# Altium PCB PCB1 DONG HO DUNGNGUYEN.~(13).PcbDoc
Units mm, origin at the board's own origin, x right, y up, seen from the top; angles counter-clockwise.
Board outline 60.96 x 45.72 mm, 2 copper layers (Top Layer, Bottom Layer); 0 components, 3 nets, 0 pads, 0 vias.
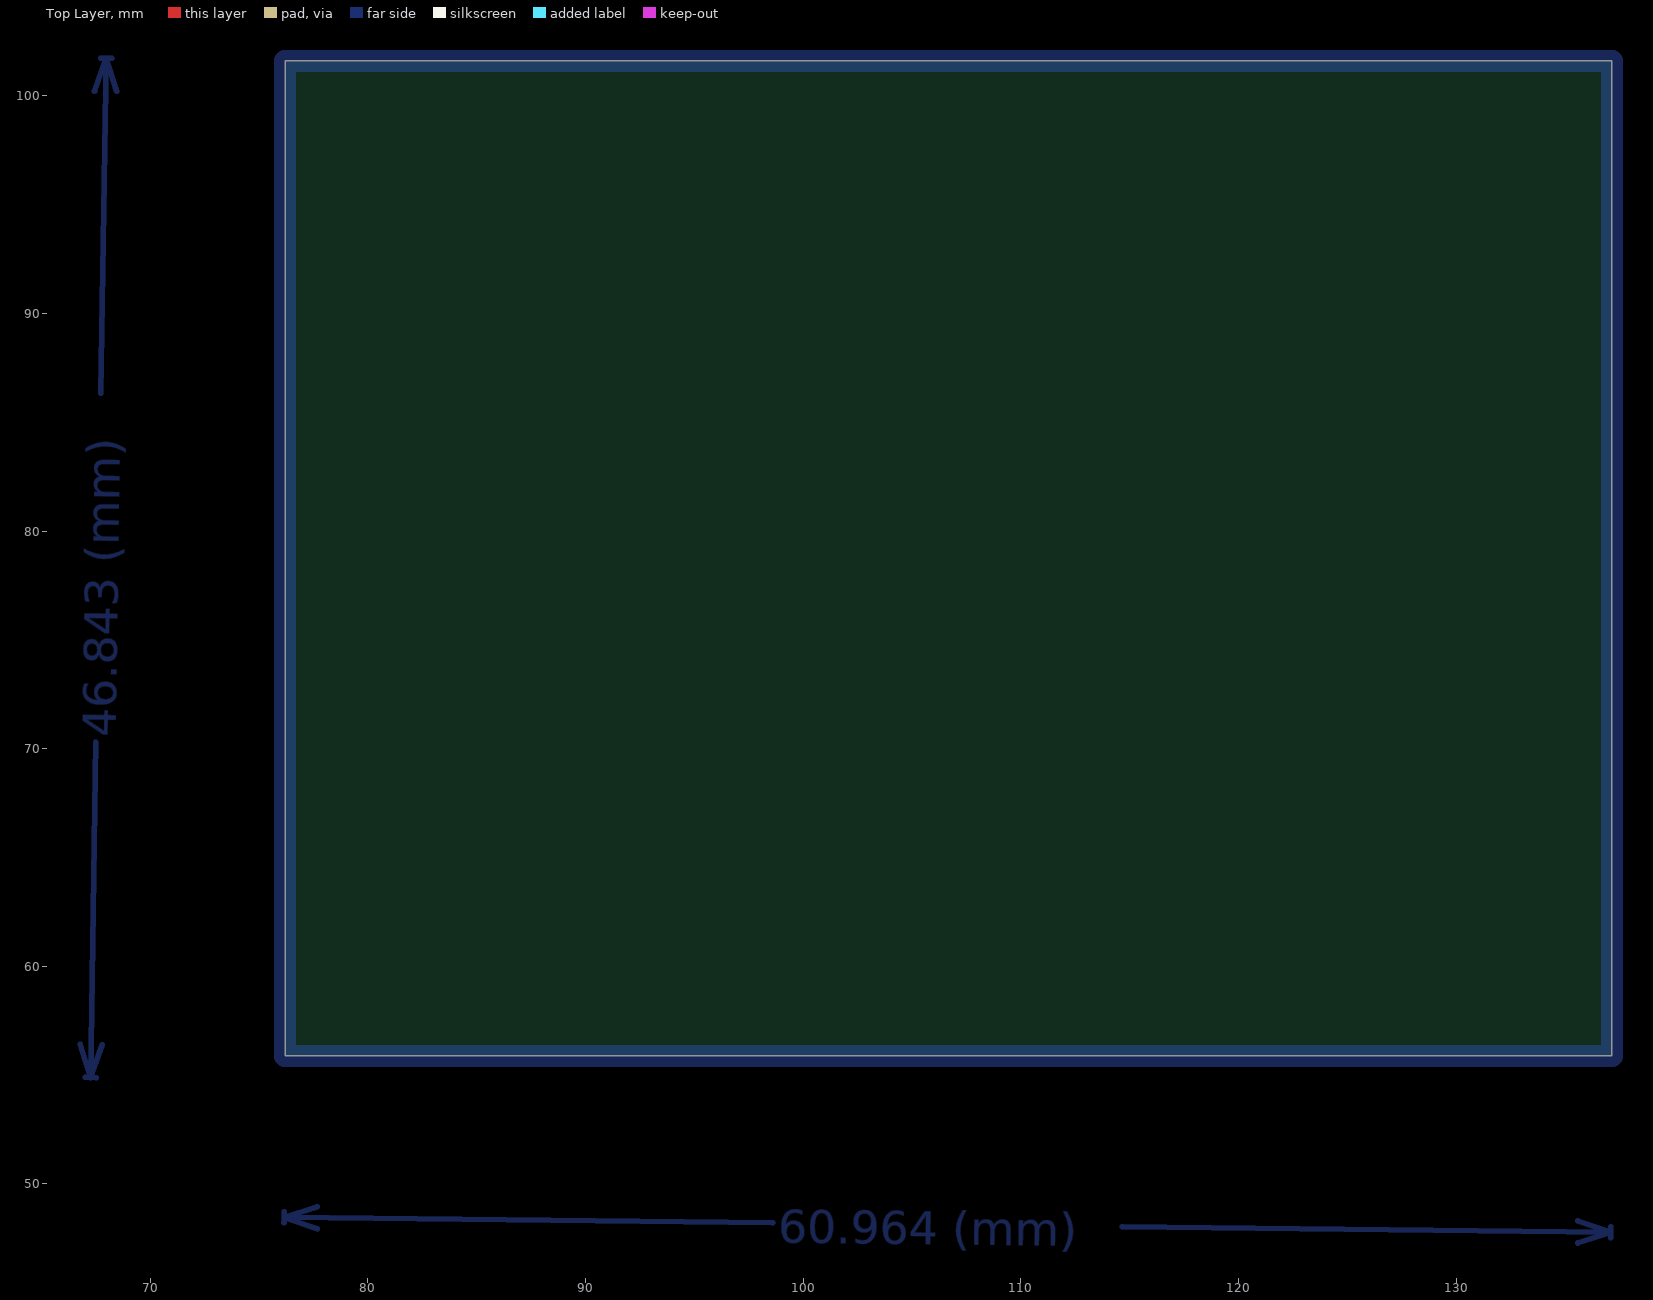
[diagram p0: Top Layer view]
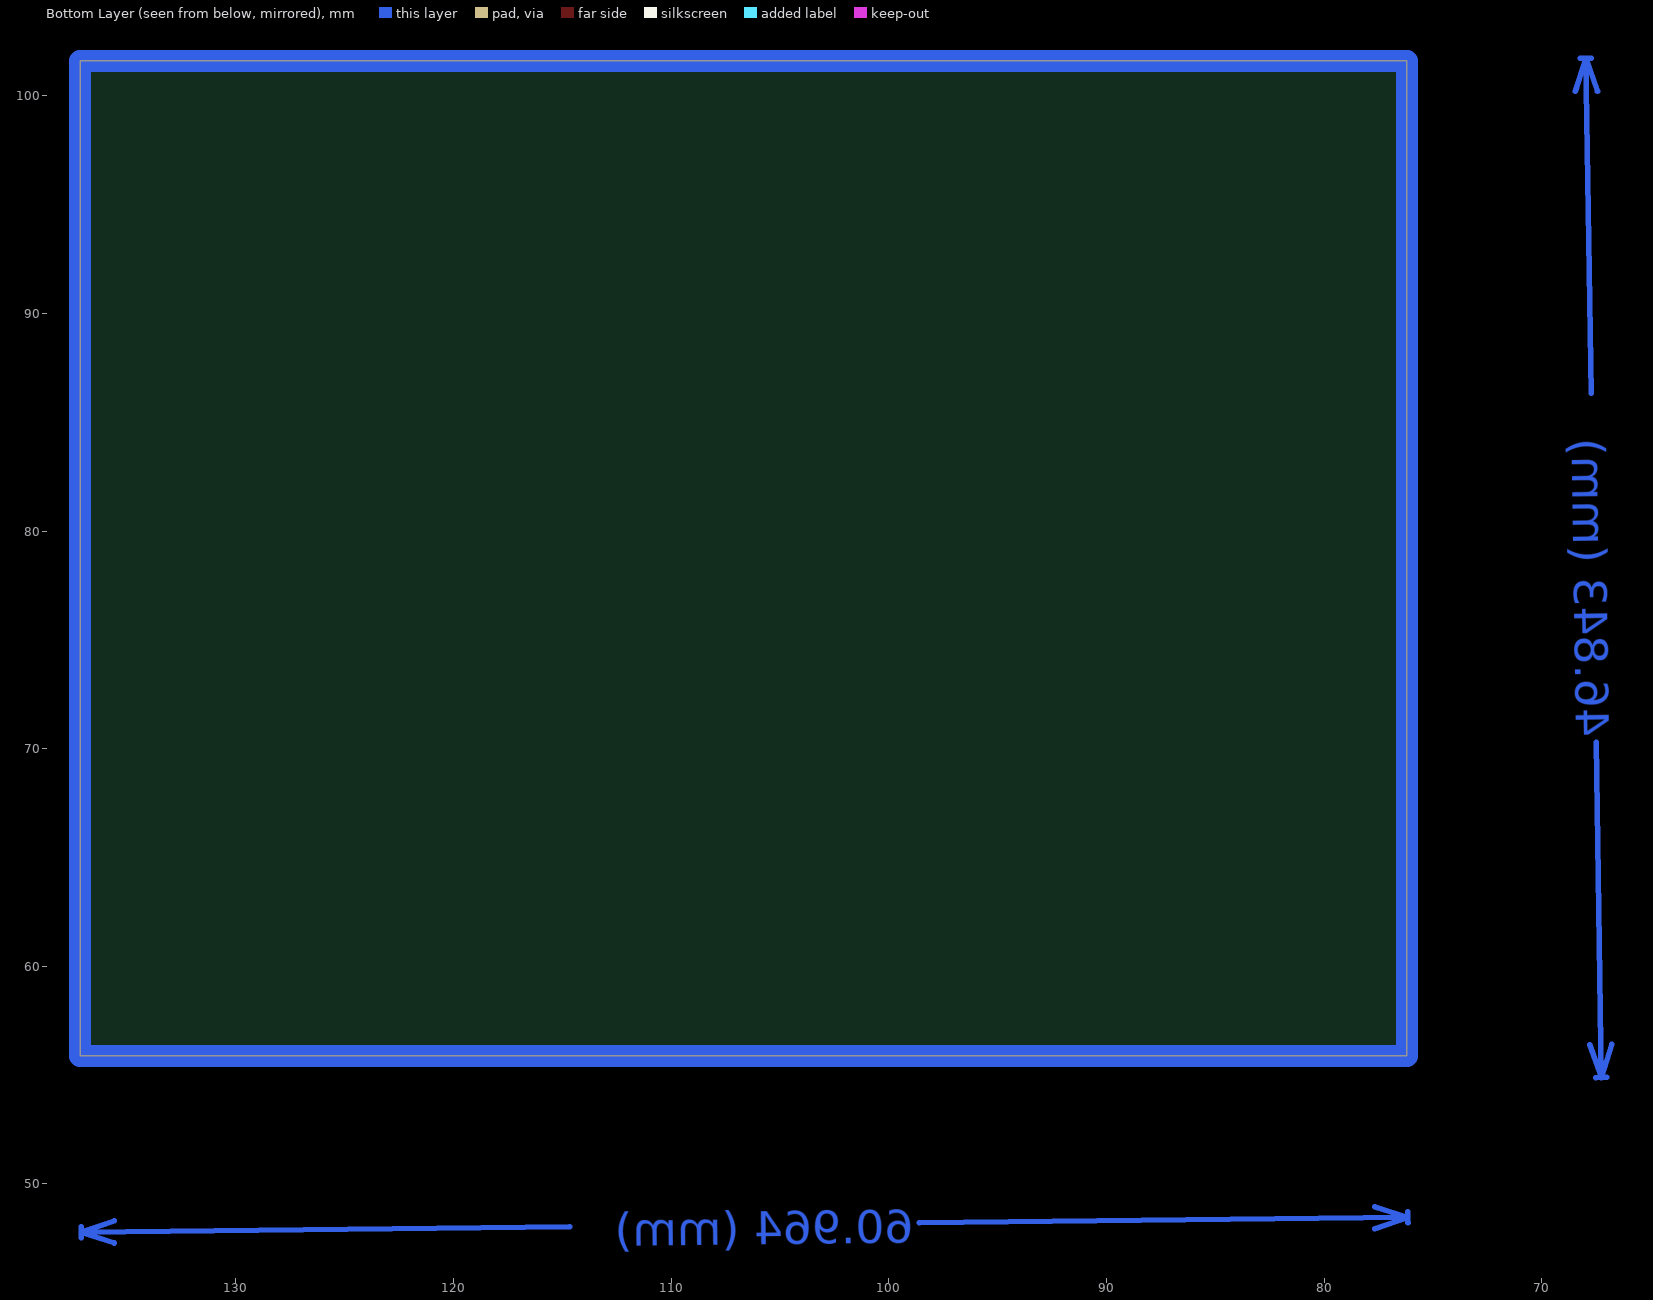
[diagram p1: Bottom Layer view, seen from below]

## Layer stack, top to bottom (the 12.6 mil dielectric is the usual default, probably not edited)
Top Solder: solder mask 0.0102, Solder Resist, Dk 3.5
Top Layer: signal copper 0.0356
Dielectric 1: dielectric 0.32, FR-4, Dk 4.8
Bottom Layer: signal copper 0.0356
Bottom Solder: solder mask 0.0102, Solder Resist, Dk 3.5

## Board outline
76.2,55.88 76.2,101.6 137.16,101.6 137.16,55.88

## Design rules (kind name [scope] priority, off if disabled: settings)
Clearance [All] p1: gap=0.254 ignorepadtopadclearanceinfootprint=FALSE except(0: Arc-Hole Track-Hole SMDPad-Hole THPad-Hole Via-Hole Fill-Hole Poly-Hole Region-Hole Text-Hole)
PolygonConnect [All] p1: connectstyle=Relief reliefconductorwidth=0.254 reliefentries=4 polygonreliefangle="90 Angle" airgapwidth=0.254
RoomDefinition DONG_HO [InComponentClass('DONG_HO')] p1: confinementstyle=ConfineIn formatcopy=TRUE lockcomponents=FALSE outline 138.303,57.277 149.25,57.277 149.25,67.132 138.303,67.132
RoutingVias [All] p1: holewidth=0.711 width=1.27 viastyle="Through Hole" minholewidth=0.711 minwidth=1.27 maxholewidth=2.54 maxwidth=2.54
SolderMaskExpansion [All] p1: expansion=0.102
Width [All] p1: maxlimit=2.032 minlimit=1.016 preferedwidth=1.524
30 further rules are at their usual default settings.

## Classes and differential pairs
component class DONG_HO: HD?

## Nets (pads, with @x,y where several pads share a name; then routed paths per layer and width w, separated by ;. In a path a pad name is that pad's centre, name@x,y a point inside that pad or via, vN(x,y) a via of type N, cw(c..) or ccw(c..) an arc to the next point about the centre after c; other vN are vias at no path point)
GND: 
"NetLED TT2_1": 
NetQ1_2: 
copper on no net: | length 304
  Bottom Layer w0.254: 66.774,56.421 67.259,54.889 ; 67.005,54.893 67.513,54.886 ; 67.439,100.211 67.97,101.727 ; 67.493,70.285 67.259,54.889 ; 67.716,101.731 68.224,101.723 ; 67.737,86.331 67.97,101.727 ; 67.79,56.406 67.259,54.889 ; 68.455,100.195 67.97,101.727 ; 76.146,48.209 76.152,48.717 ; 77.667,47.938 76.149,48.463 ; 77.679,48.954 76.149,48.463 ; 98.606,48.211 76.149,48.463 ; 114.653,48.03 137.109,47.777 ; 135.58,47.287 137.109,47.777 ; 135.591,48.303 137.109,47.777 ; 137.106,47.523 137.112,48.031
  Bottom Layer w1.016: 76.2,55.88 76.2,101.6 137.16,101.6 137.16,55.88 76.2,55.88

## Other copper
Bottom Layer:
  text "46.843 (mm)" at 68.411,70.525 h1.52 r89.13
  text "60.964 (mm)" at 98.849,47.294 h1.52 r359.36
